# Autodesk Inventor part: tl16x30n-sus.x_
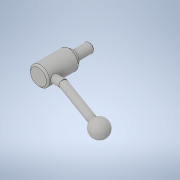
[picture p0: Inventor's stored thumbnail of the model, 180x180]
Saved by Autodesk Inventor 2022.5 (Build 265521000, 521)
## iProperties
Created: 2021-02
Part Number: tl16x30n-sus.x_
Material: 一般
Document SubType Name: Modeling
Designer: ImaoCorp
Density: 1 g/cm^3
Appearance: 既定
Sending System: SOLIDWORKS 2019-2019304
MC: AMD64
MC_MODEL: Intel64 Family 6 Model 60 Stepping 3, GenuineIntel
OS: Windows_NT
FRU: Parasolid Version 31.0, build 290,  9- 1-2019
FORMAT: text
GUISE: transmit
KEY: tl16x30n-sus
FILE: tl16x30n-sus.x_t
DATE: Mon Feb 22 14:52:15 2021
Author: ImaoCorp
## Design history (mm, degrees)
feature "Base1"
node "ソリッド1"
